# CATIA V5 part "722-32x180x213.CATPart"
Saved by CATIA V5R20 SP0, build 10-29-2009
Part number: 722-32x180x213
Definition: NONE
Nomenclature: 722-32x180x213
Source: Unknown
Description: 722-32x180x213
Bounding box of the stored display mesh (mm): x -16 to 16, y -16 to 16, z -165 to 48
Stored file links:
  C:\Users\Utente\Desktop\IO LAVORO\3D X SITO CF\X SITO\722\722-32x180x213.CATPart

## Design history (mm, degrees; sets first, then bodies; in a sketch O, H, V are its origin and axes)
Body1 "722-32x180x213" (main body)
  Solid1: solid without history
